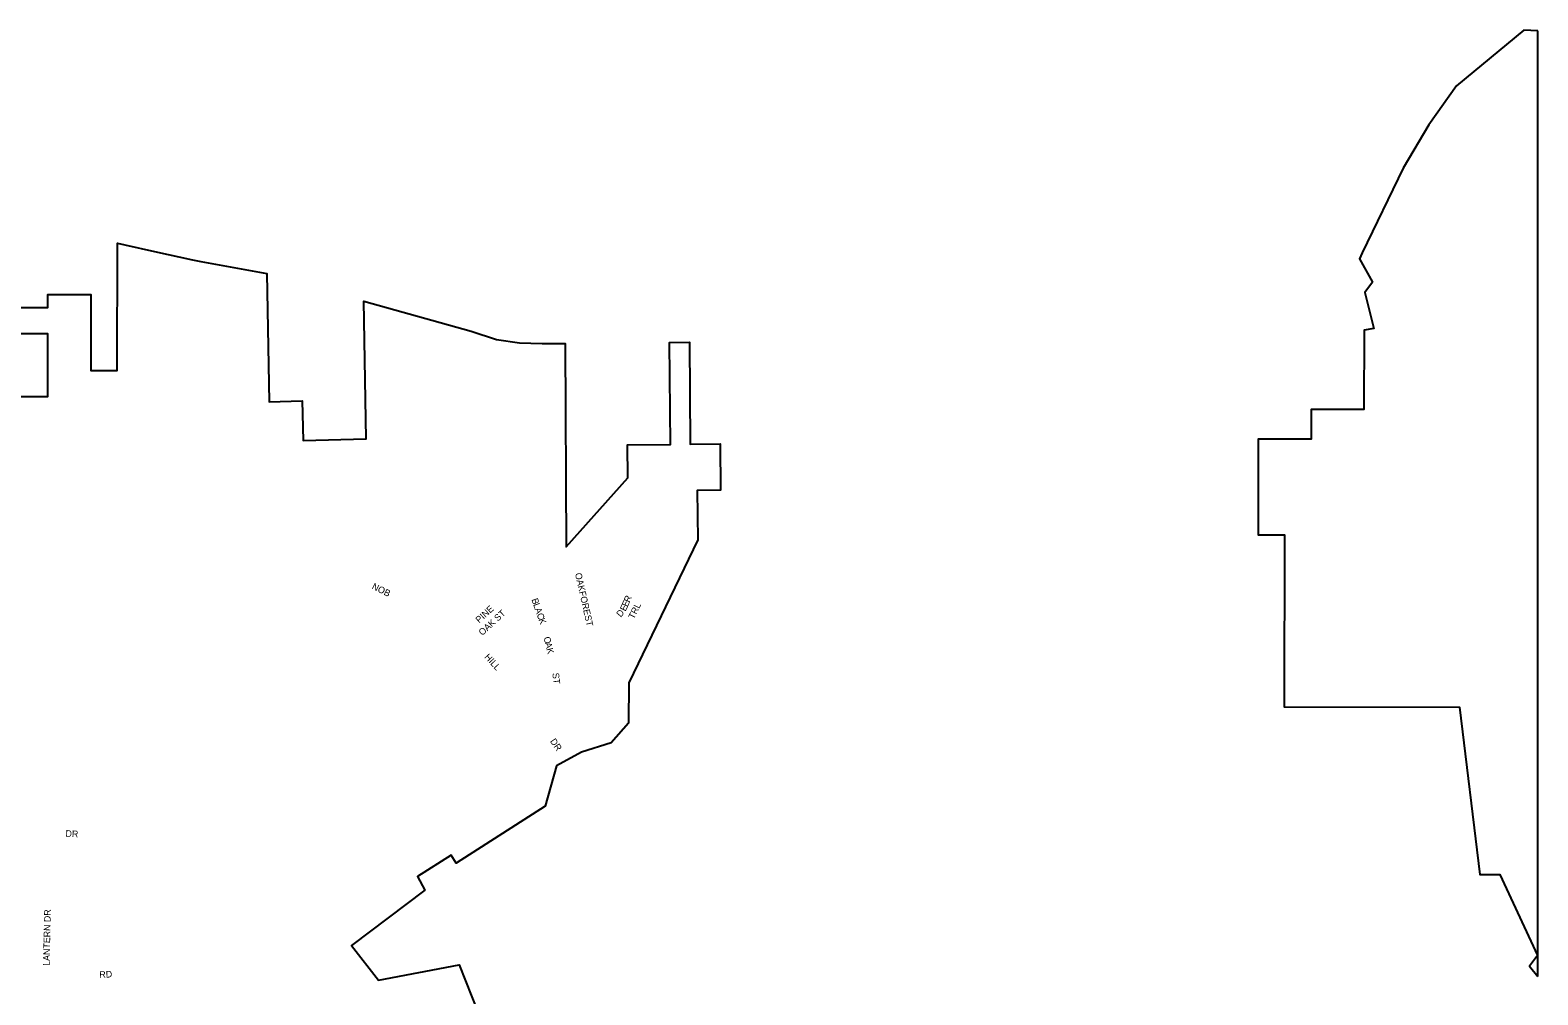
# Model space of a CAD drawing. Extents: x 0 to 34, y -0.1 to 32.4.
# Drawn here: x 7.58 to 9.74, y 28.217 to 29.599 of the extents above; entities that cross this region are included whole.
import ezdxf

# ---------------------------------------------------------------- set-up
doc = ezdxf.new("R2010")
doc.units = 0
doc.layers.add('GM_X_Interchange_Ramps', color=7, linetype='Continuous')
doc.layers.add('GM_X_US_Shield', color=7, linetype='Continuous')

msp = doc.modelspace()

# ---------------------------------------------------------------- linework, layer by layer
at = {"layer": 'GM_X_Interchange_Ramps'}
msp.add_line((9.7404, 28.2434), (9.7404, 29.5985), dxfattribs=at)
for points in [[(9.7404, 29.5985), (9.7205, 29.5995), (9.6236, 29.5198), (9.5842, 29.4636), (9.5473, 29.4018), (9.4888, 29.2805), (9.4849, 29.2717), (9.5034, 29.2383), (9.4925, 29.2234), (9.5056, 29.172), (9.4914, 29.1695), (9.4913, 29.0558), (9.4155, 29.0559), (9.4155, 29.0133), (9.3397, 29.0134), (9.3395, 28.8762), (9.3774, 28.8762), (9.3771, 28.6299), (9.6282, 28.6296), (9.6574, 28.3898), (9.6858, 28.3898), (9.7399, 28.2735), (9.7285, 28.2583), (9.7404, 28.2434)], [(7.482, 29.2021), (7.6059, 29.202), (7.6059, 29.2209), (7.6675, 29.2209), (7.6674, 29.1119), (7.7053, 29.1119), (7.7055, 29.2942), (7.7162, 29.2918), (7.7587, 29.2824), (7.8129, 29.2705), (7.8251, 29.2678), (7.9194, 29.2507), (7.9228, 29.0667), (7.9701, 29.0681), (7.9718, 29.0113), (8.0618, 29.0139), (8.0585, 29.211), (8.2121, 29.1682), (8.2485, 29.1561), (8.2816, 29.1512), (8.314, 29.1504), (8.3471, 29.1504), (8.3482, 28.8592), (8.4366, 28.9579), (8.4362, 29.0053), (8.4977, 29.0059), (8.4964, 29.152), (8.5248, 29.1523), (8.5262, 29.0061), (8.5688, 29.0065), (8.5694, 28.9402), (8.5362, 28.9399), (8.5369, 28.8693), (8.4383, 28.6643), (8.4375, 28.6063), (8.4129, 28.5784), (8.3703, 28.5651), (8.3345, 28.5454), (8.3184, 28.4873), (8.1906, 28.4059), (8.1835, 28.4171), (8.1355, 28.3866), (8.1458, 28.3673), (8.041, 28.2878), (8.0794, 28.2381), (8.1952, 28.26), (8.2493, 28.1227)], [(7.4779, 29.0744), (7.6058, 29.0743), (7.6059, 29.1641), (7.4827, 29.1642)]]:
    msp.add_lwpolyline(points, dxfattribs=at)

# ---------------------------------------------------------------- texts
at = {"layer": 'GM_X_US_Shield'}
for s, rotation, p in [('OAKFOREST', 282.6815, (8.3609, 28.8207)), ('NOB', 333.4316, (8.0691, 28.7994)), ('PINE', 42.3988, (8.2238, 28.7492)), ('B', 289.7175, (8.2984, 28.7835)), ('L', 289.7007, (8.3009, 28.7764)), ('A', 289.7135, (8.3031, 28.7701)), ('E', 64.0891, (8.4333, 28.766)), ('E', 65.9647, (8.4363, 28.7723)), ('R', 67.7877, (8.4392, 28.7787)), ('TRL', 63.4404, (8.4453, 28.7548)), ('OAK ST', 42.5818, (8.2282, 28.7313)), ('C', 289.7219, (8.3059, 28.7623)), ('K', 290.7514, (8.3085, 28.755)), ('D', 49.6571, (8.4265, 28.7575)), ('O', 284.1078, (8.3159, 28.7291)), ('HILL', 312.5094, (8.2305, 28.7007)), ('A', 284.0866, (8.3179, 28.721)), ('K', 284.101, (8.32, 28.713)), ('ST', 277.1361, (8.3285, 28.678)), ('DR', 304.5019, (8.3248, 28.5805)), ('DR', 356.8222, (7.6309, 28.4438)), ('LANTERN DR', 88.6987, (7.6083, 28.2587)), ('RD', 3.0116, (7.6799, 28.2413))]:
    msp.add_text(s, height=0.00947, rotation=rotation, dxfattribs=at).set_placement(p)

doc.saveas('drawing.dxf')
